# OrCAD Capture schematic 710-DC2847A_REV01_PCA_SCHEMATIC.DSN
size Custom; note: 9KHZ-7GHz SCALAR REFLECTOMETER
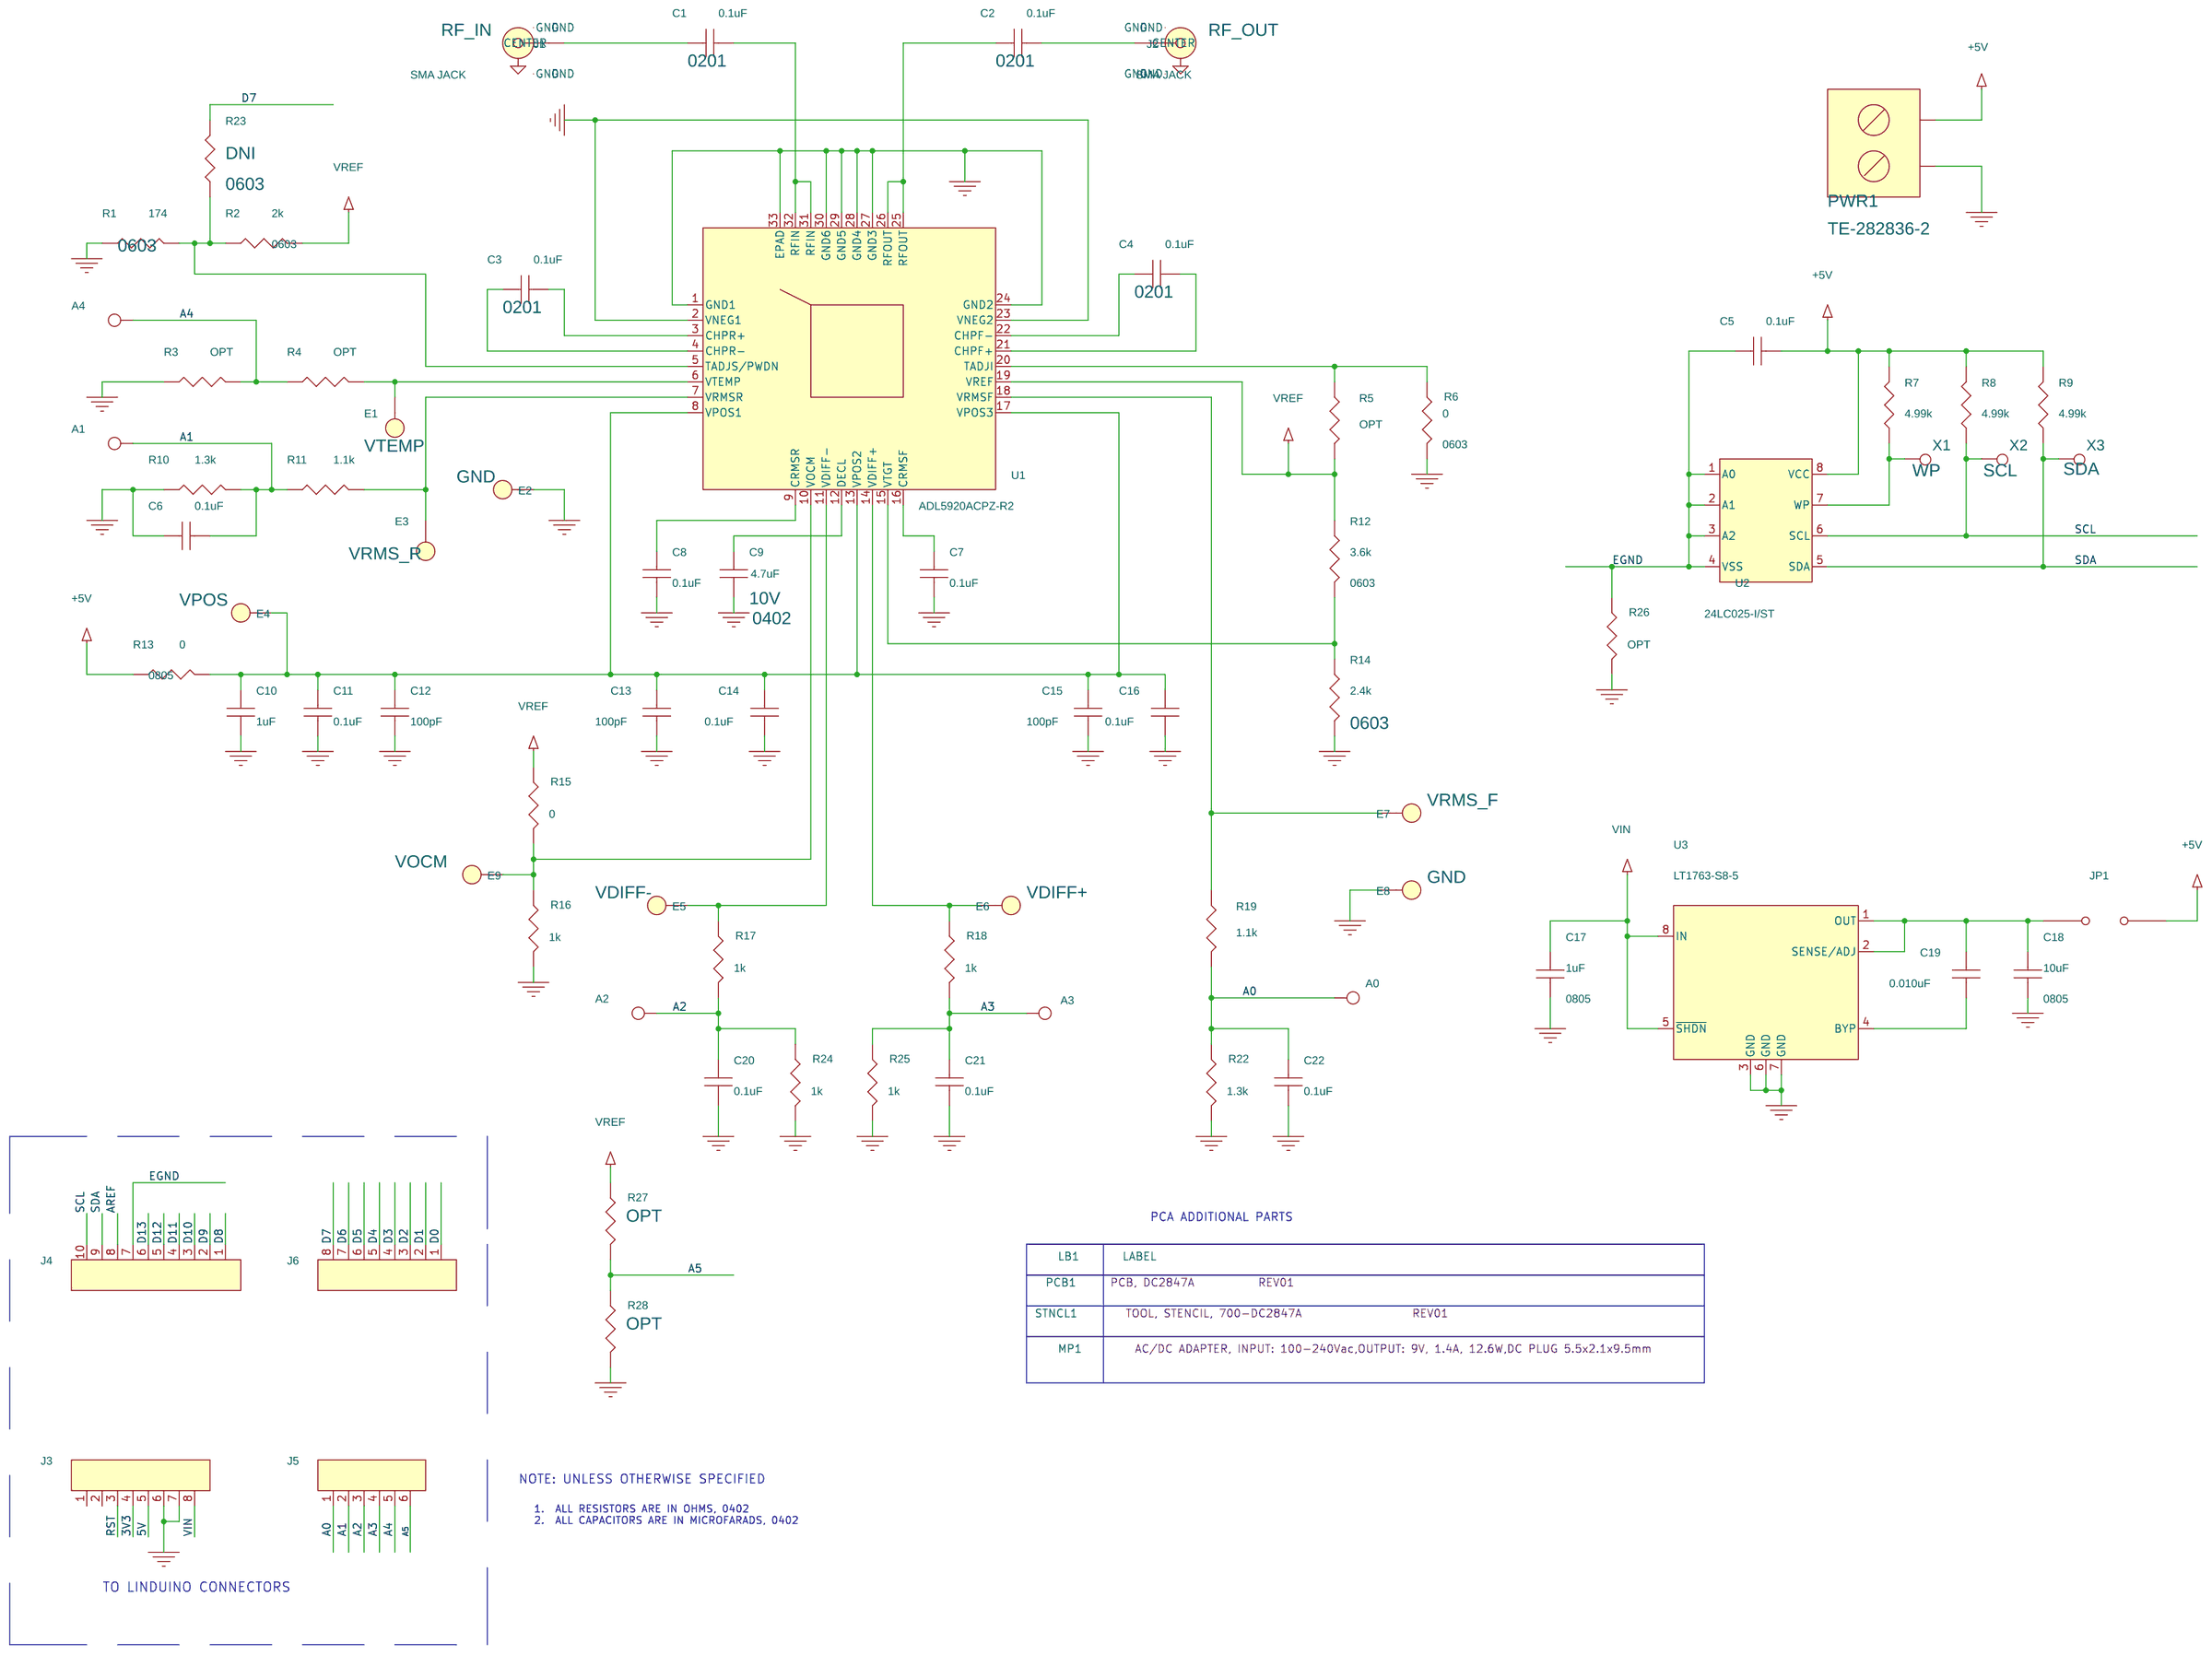
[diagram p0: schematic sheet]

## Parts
A0  PAD060-SMT-T  [PAD060-SMT-T]
A1  PAD060-SMT-T  [PAD060-SMT-T]
A2  PAD060-SMT-T  [PAD060-SMT-T]
A3  PAD060-SMT-T  [PAD060-SMT-T]
A4  PAD060-SMT-T  [PAD060-SMT-T]
C1  0.1uF  [CC0201N]
C2  0.1uF  [CC0201N]
C3  0.1uF  [CC0201N]
C4  0.1uF  [CC0201N]
C5  0.1uF  [CC0402N]
C6  0.1uF  [CC0402N]
C7  0.1uF  [CC0402N]
C8  0.1uF  [CC0402N]
C9  4.7uF  [CC0402N]
C10  1uF  [CC0402N]
C11  0.1uF  [CC0402N]
C12  100pF  [CC0402N]
C13  100pF  [CC0402N]
C14  0.1uF  [CC0402N]
C15  100pF  [CC0402N]
C16  0.1uF  [CC0402N]
C17  1uF  [CC0805N]
C18  10uF  [CC0805N]
C19  0.010uF  [CC0402N]
C20  0.1uF  [CC0402N]
C21  0.1uF  [CC0402N]
C22  0.1uF  [CC0402N]
E1  TEST POINT  [MILLMAX2308]
E2  TEST POINT  [MILLMAX2308]
E3  TEST POINT  [MILLMAX2308]
E4  TEST POINT  [MILLMAX2308]
E5  TEST POINT  [MILLMAX2308]
E6  TEST POINT  [MILLMAX2308]
E7  TEST POINT  [MILLMAX2308]
E8  TEST POINT  [MILLMAX2308]
E9  TEST POINT  [MILLMAX2308]
J1  SMA JACK  [CINCH-142-0761-871]
J2  SMA JACK  [CINCH-142-0761-871]
J3  SOCKET HDR.  [SAMTEC-SSQ-STR-1X8]
J4  SOCKET HDR.  [SAMTEC-SSQ-STR-1X10]
J5  SOCKET HDR.  [HD1X6-100]
J6  SOCKET HDR.  [SAMTEC-SSQ-STR-1X8]
JP1  HDR  [HD1X2-079]
LB1  LABEL  [895-0154_REV01]
MP1  AC/DC ADAPTER
PCB1  PCB, DC2847A
PWR1  TERM. BLOCK  [TE-282836-2]
R1  174  [CR0603N]
R2  2k  [CR0603N]
R3  OPT  [CR0402N]
R4  OPT  [CR0402N]
R5  OPT  [CR0402N]
R6  0  [CR0603N]
R7  4.99k  [CR0402N]
R8  4.99k  [CR0402N]
R9  4.99k  [CR0402N]
R10  1.3k  [CR0402N]
R11  1.1k  [CR0402N]
R12  3.6k  [CR0603N]
R13  0  [CR0805N]
R14  2.4k  [CR0603N]
R15  0  [CR0402N]
R16  1k  [CR0402N]
R17  1k  [CR0402N]
R18  1k  [CR0402N]
R19  1.1k  [CR0402N]
R22  1.3k  [CR0402N]
R23  OPT  [CR0603N]
R24  1k  [CR0402N]
R25  1k  [CR0402N]
R26  OPT  [CR0402N]
R27  OPT  [CR0402N]
R28  OPT  [CR0402N]
STNCL1  TOOL, STENCIL, 700-DC2847A
U1  ADL5920ACPZ-R2  [ADI-CP-32-7]
U2  24LC025-I/ST  [MICROCHIP-TSSOP-8]
U3  LT1763-S8-5  [LTC-S8-8-1610(S8)]
X1  E-SMT-060  [PAD060-SMT-T]
X2  E-SMT-060  [PAD060-SMT-T]
X3  E-SMT-060  [PAD060-SMT-T]

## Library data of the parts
A0-A4 = E-SMT-060_2
C1-C4 = CAP: CAP.,0.1uF,RF,16V,10%,0201; CLASS: DISCRETE; Dielectric Type: RF; Manufacturer: PASSIVE PLUS, INC.; Manufacturer PN: 0201BB104KW160; PART_NUMBER: 150-0683; Package Size: 0201; Rated Voltage: 16V; Tolerance: 10%
C5-C8 C11 C14 C16 C20-C22 = CAP: CAP.,0.1uF,X5R,50V,10%,0402; CLASS: DISCRETE; Dielectric Type: X5R; FPLIST: CC0402N,CC0402L,CC0402M; Manufacturer: AVX; Manufacturer PN: 04025D104KAT2A; PART_NUMBER: 150-3561; Package Size: 0402; Package Type: Surface Mount, MLCC; Rated Voltage: 50V; Temperature Coefficient: X5R; Tolerance: 10%
C9 = CAP: CAP.,4.7uF,X5R,10V,10%,0402; CLASS: DISCRETE; Dielectric Type: X5R; FPLIST: CC0402N,CC0402L,CC0402M; Manufacturer: TDK; Manufacturer PN: C1005X5R1A475K050BC; PART_NUMBER: 150-2275; Package Size: 0402; Rated Voltage: 10V; Tolerance: 10%
C10 = CAP: CAP.,1uF,X5R,10V,10%,0402; CLASS: DISCRETE; Dielectric Type: X5R; FPLIST: CC0402N,CC0402L,CC0402M; Manufacturer: MURATA; Manufacturer PN: GRM155R61A105KE15D; PART_NUMBER: 150-3493; Package Size: 0402; Rated Voltage: 10V; Tolerance: 10%
C12 C13 C15 = CAP: CAP.,100pF,X7R,50V,10%,0402; CLASS: DISCRETE; Dielectric Type: X7R; FPLIST: CC0402N,CC0402L,CC0402M; Manufacturer: AVX; Manufacturer PN: 04025C101KAT2A; PART_NUMBER: 150-2079; Package Size: 0402; Rated Voltage: 50V; Tolerance: 10%
C17 = CAP: CAP.,1uF,X7R,10V,10%,0805; CLASS: DISCRETE; Dielectric Type: X7R; FPLIST: CC0805N,CC0805L,CC0805M; Manufacturer: AVX; Manufacturer PN: 0805ZC105KAT2A; PART_NUMBER: 150-0141; Package Size: 0805; Rated Voltage: 10V; Tolerance: 10%
C18 = CAP: CAP.,10uF,X5R,10V,10%,0805; CLASS: DISCRETE; Dielectric Type: X5R; FPLIST: CC0805N,CC0805L,CC0805M; Manufacturer: MURATA; Manufacturer PN: GRM21BR61A106KE19L; PART_NUMBER: 150-0224; Package Size: 0805; Rated Voltage: 10V; Tolerance: 10%
C19 = CAP: CAP.,0.010uF,X7R,25V,10%,0402; CLASS: DISCRETE; Dielectric Type: X7R; FPLIST: CC0402N,CC0402L,CC0402M; Manufacturer: KEMET; Manufacturer PN: C0402C103K3RACTU; PART_NUMBER: 150-0477; Package Size: 0402; Rated Voltage: 25V; Tolerance: 10%
E1 = TEST_POINT_.156_MILL-MAX_2308: TEST POINT,TURRET,0.064",MTG. HOLE; 1: VTEMP; CLASS: IO; Manufacturer: MILL-MAX; Manufacturer PN: 2308-2-00-80-00-00-07-0; PART_NUMBER: 260-0004
E2 E8 = TEST_POINT_.156_MILL-MAX_2308: TEST POINT,TURRET,0.064",MTG. HOLE; 1: GND; CLASS: IO; Manufacturer: MILL-MAX; Manufacturer PN: 2308-2-00-80-00-00-07-0; PART_NUMBER: 260-0004
E3 = TEST_POINT_.156_MILL-MAX_2308: TEST POINT,TURRET,0.064",MTG. HOLE; 1: VRMS_R; CLASS: IO; Manufacturer: MILL-MAX; Manufacturer PN: 2308-2-00-80-00-00-07-0; PART_NUMBER: 260-0004
E4 = TEST_POINT_.156_MILL-MAX_2308: TEST POINT,TURRET,0.064",MTG. HOLE; 1: VPOS; CLASS: IO; Manufacturer: MILL-MAX; Manufacturer PN: 2308-2-00-80-00-00-07-0; PART_NUMBER: 260-0004
E5 = TEST_POINT_.156_MILL-MAX_2308: TEST POINT,TURRET,0.064",MTG. HOLE; 1: VDIFF-; CLASS: IO; Manufacturer: MILL-MAX; Manufacturer PN: 2308-2-00-80-00-00-07-0; PART_NUMBER: 260-0004
E6 = TEST_POINT_.156_MILL-MAX_2308: TEST POINT,TURRET,0.064",MTG. HOLE; 1: VDIFF+; CLASS: IO; Manufacturer: MILL-MAX; Manufacturer PN: 2308-2-00-80-00-00-07-0; PART_NUMBER: 260-0004
E7 = TEST_POINT_.156_MILL-MAX_2308: TEST POINT,TURRET,0.064",MTG. HOLE; 1: VRMS_F; CLASS: IO; Manufacturer: MILL-MAX; Manufacturer PN: 2308-2-00-80-00-00-07-0; PART_NUMBER: 260-0004
E9 = TEST_POINT_.156_MILL-MAX_2308: TEST POINT,TURRET,0.064",MTG. HOLE; 1: VOCM; CLASS: IO; Manufacturer: MILL-MAX; Manufacturer PN: 2308-2-00-80-00-00-07-0; PART_NUMBER: 260-0004
J1 = CONN_SMA_5PIN: CONN.,SMA JACK,RCPT,END LAUNCH,STR, 50 OHMS, Au; 1: RF_IN; CLASS: IO; Manufacturer: CINCH/ BEL; Manufacturer PN: 142-0761-871; PART_NUMBER: 250-0775
J2 = CONN_SMA_5PIN: CONN.,SMA JACK,RCPT,END LAUNCH,STR, 50 OHMS, Au; 1: RF_OUT; CLASS: IO; Manufacturer: CINCH/ BEL; Manufacturer PN: 142-0761-871; PART_NUMBER: 250-0775
J3 J6 = CON8: CONN.,SOCKET HDR.,RCPT,1x8,2.54mm,VERT, STR, THT,10mm CT LGTH, Au; CLASS: IO; FPLIST: SAMTEC-SSQ-STR-1X8,HD1X8-100; Manufacturer: SAMTEC; Manufacturer PN: SSQ-108-03-G-S; PART_NUMBER: 250-0895
J4 = CON-SOCKET-1X10-2.54MM: CONN.,SOCKET HDR.,RCPT.,1x10,2.54mm,VERT, STR, THT,10mm CT LGTH, Au; CLASS: IO; Manufacturer: SAMTEC; Manufacturer PN: SSQ-110-03-G-S; PART_NUMBER: 250-0894
J5 = CON6: CONN.,SOCKET HDR.,RCPT,1x6,2.54mm,VERT, STR, THT,10mm CT LGTH, Au; CLASS: IO; FPLIST: SAMTEC-SSQ-STR-1X6,HD1X6-100; Manufacturer: SAMTEC; Manufacturer PN: SSQ-106-03-G-S; PART_NUMBER: 250-0896
JP1 = JUMPER_2_PIN_.079: CONN.,HDR,MALE,1x2,2mm,VERT, STR, THT,10u" AU; CLASS: IO; Manufacturer: SAMTEC; Manufacturer PN: TMM-102-02-L-S; PART_NUMBER: 250-0420
LB1 = BLANK_LABEL: LABEL SPEC, DEMO BOARD SERIAL NUMBER; Manufacturer: BRADY; Manufacturer PN: THT-96-717-10; PART_NUMBER: 895-0154
MP1 = BLANK_PINLESS_MECHANICAL_PART: AC/DC ADAPTER, INPUT: 100-240Vac,OUTPUT: 9V, 1.4A, 12.6W,DC PLUG 5.5x2.1x9.5mm; CLASS: IO; Manufacturer: CUI INC.; Manufacturer PN: SWI15-9-N-P5; PART_NUMBER: 920-0055
PCB1 = BLANK_PCB_PART: BOM Notes: REV01; CLASS: DISCRETE; Manufacturer: GORILLA CIRCUITS; Manufacturer PN: 600-DC2847A; PART_NUMBER: 600-DC2847A
PWR1 = TERMINAL_BLOCK_WITH_SCREW: CONN.,TERM. BLOCK,RCPT,1x2,5mm,SIDE ENTRY, THT; CLASS: IO; Manufacturer: TE CONNECTIVITY; Manufacturer PN: 282836-2; PART_NUMBER: 250-0752
R1 = RES: RES.,174 OHMS,1%,1/10W,0603,AEC-Q200; CLASS: DISCRETE; Manufacturer: PANASONIC; Manufacturer PN: ERJ3EKF1740V; PART_NUMBER: 100-1100; Package Size: 0603; Rated Power: 1/10W; Temperature Coefficient: 100ppm; Tolerance: 1%
R2 = RES: RES.,2k OHMS,1%,1/10W,0603; CLASS: DISCRETE; FPLIST: CR0603N,CR0603L,CR0603M; Manufacturer: NIC; Manufacturer PN: NRC06F2001TRF; PART_NUMBER: 100-2313; Package Size: 0603; Rated Power: 1/10W; Temperature Coefficient: 100ppm/C; Tolerance: 1%
R3-R5 R26 = RES: RES., OPTION, 0402; CLASS: DISCRETE; FPLIST: CR0402N,CR0402L,CR0402M; PART_NUMBER: 100-0357; Package Size: 0402
R6 = RES: RES.,0 OHM,1/10W,0603; CLASS: DISCRETE; FPLIST: CR0603N,CR0603L,CR0603M; Manufacturer: YAGEO; Manufacturer PN: RC0603FR-070RL; PART_NUMBER: 100-2621; Package Size: 0603; Rated Power: 1/10W
R7-R9 = RES: RES.,4.99k OHMS,1%,1/16W,0402; CLASS: DISCRETE; FPLIST: CR0402N,CR0402L,CR0402M; Manufacturer: NIC; Manufacturer PN: NRC04F4991TRF; PART_NUMBER: 100-2625; Package Size: 0402; Rated Power: 1/16W; Temperature Coefficient: 100ppm/C; Tolerance: 1%
R10 R22 = RES: RES.,1.3k OHMS,1%,1/16W,0402,AEC-Q200; CLASS: DISCRETE; Manufacturer: NIC; Manufacturer PN: NRC04F1301TRF; PART_NUMBER: 100-1101; Package Size: 0402; Rated Power: 1/16W; Temperature Coefficient: +/-100PPM; Tolerance: 1%
R11 R19 = RES: RES.,1.1k OHMS,1%,1/16W,0402,AEC-Q200; CLASS: DISCRETE; FPLIST: CR0402N,CR0402L,CR0402M; Manufacturer: NIC; Manufacturer PN: NRC04F1101TRF; PART_NUMBER: 100-2638; Package Size: 0402; Rated Power: 1/16W; Temperature Coefficient: 100ppm/C; Tolerance: 1%
R12 = RES: RES.,3.6k OHMS,1%,1/10W,0603,AEC-Q200; CLASS: DISCRETE; FPLIST: CR0603N,CR0603L,CR0603M; Manufacturer: PANASONIC; Manufacturer PN: ERJ3EKF3601V; PART_NUMBER: 100-0110; Package Size: 0603; Rated Power: 1/10W; Temperature Coefficient: 100ppm/C; Tolerance: 1%
R13 = RES: RES.,0 OHM,1/8W,0805; CLASS: DISCRETE; FPLIST: CR0805N,CR0805L,CR0805M; Manufacturer: YAGEO; Manufacturer PN: RC0805JR-070RL; PART_NUMBER: 100-2291; Package Size: 0805; Rated Power: 1/8W; Temperature Coefficient: 300ppm
R14 = RES: RES.,2.4k OHMS,1%,1/10W,0603,AEC-Q200; CLASS: DISCRETE; Manufacturer: PANASONIC; Manufacturer PN: ERJ3EKF2401V; PART_NUMBER: 100-1102; Package Size: 0603; Rated Power: 1/10W; Temperature Coefficient: +/-100PPM; Tolerance: 1%
R15 = RES: RES.,0 OHM,1/16W,0402; CLASS: DISCRETE; FPLIST: CR0402N,CR0402L,CR0402M; Manufacturer: NIC; Manufacturer PN: NRC04ZOTRF; PART_NUMBER: 100-0025; Package Size: 0402; Rated Power: 1/16W
R16-R18 R24 R25 = RES: RES.,1k OHMS,1%,1/16W,0402; CLASS: DISCRETE; FPLIST: CR0402N,CR0402L,CR0402M; Manufacturer: NIC; Manufacturer PN: NRC04F1001TRF; PART_NUMBER: 100-2861; Package Size: 0402; Rated Power: 1/16W; Temperature Coefficient: +/-100ppm; Tolerance: 1%
R23 = RES: RES., OPTION, 0603; BOM Notes: DNI; CLASS: DISCRETE; FPLIST: CR0603N,CR0603L,CR0603M; PART_NUMBER: 100-2374; Package Size: 0603
R27 R28 = RES: RES., OPTION, 0402; BOM Notes: DNI; CLASS: DISCRETE; FPLIST: CR0402N,CR0402L,CR0402M; PART_NUMBER: 100-0357; Package Size: 0402
STNCL1 = BLANK_STENCIL_PART: BOM Notes: REV01; CLASS: DISCRETE; Manufacturer: ANALOG DEVICES INC.; Manufacturer PN: 830-DC2847A; PART_NUMBER: 830-DC2847A
U1 = ADL5920: IC,9KHz-7GHz Directional Bridge and Dual RMS Detector; CLASS: IC; Manufacturer: ANALOG DEVICES INC.
U2 = 24LC025-I_ST_TSSOP-8: IC, MEMORY,EEPROM,2Kb (256x8),TSSOP-8,400kHz; CLASS: IC; Manufacturer: Microchip; PART_NUMBER: 380-0087; Package Size: TSSOP-8; Package Type: TSSOP-8
U3 = LT1763-S8-X: IC,LDO uPOWER REGULATOR,SO-8; CLASS: IC; Manufacturer: LINEAR TECH.; Manufacturer PN: LT1763CS8-5#PBF; PART_NUMBER: LT1763CS8-5#PBF; Package Type: SO-8
X1 = E-SMT-060_0: 1: WP
X2 = E-SMT-060_0: 1: SCL
X3 = E-SMT-060_0: 1: SDA

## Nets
3V3: J3.4
5V: J3.5
+5V: C5.2 JP1.2 PWR1.1 R7.2 R8.2 R9.2 R13.1 U2.8(VCC)
GND: C6.1 C7.2 C8.2 C9.2 C10.2 C11.2 C12.2 C13.2 C14.2 C15.2 C16.2 C17.2 C18.2 C20.2 C21.2 C22.2 E2.1(A) E8.1(A) J1.2(GND) J1.3(GND) J1.4(GND) J1.5(GND) J2.2(GND) J2.3(GND) J2.4(GND) J2.5(GND) J3.6 J3.7 PWR1.2 R1.1 R3.1 R6.2 R10.1 R14.2 R16.2 R22.2 R24.2 R25.2 R26.2 R28.2 U1.1(GND1) U1.2(VNEG1) U1.23(VNEG2) U1.24(GND2) U1.27(GND3) U1.28(GND4) U1.29(GND5) U1.30(GND6) U1.33(EPAD) U3.3(GND) U3.6(GND) U3.7(GND)
VIN: C17.1 J3.8 U3.5(~{SHDN}) U3.8(IN)
A0: A0.1 C22.1 J5.1 R19.2 R22.1
A1: A1.1 C6.2 J5.2 R10.2 R11.1
A2: A2.1 C20.1 J5.3 R17.2 R24.1
A3: A3.1 C21.1 J5.4 R18.2 R25.1
A4: A4.1 J5.5 R3.2 R4.1
A5: J5.6 R27.2 R28.1
AREF: J4.8
D0: J6.1
D1: J6.2
D2: J6.3
D3: J6.4
D4: J6.5
D5: J6.6
D6: J6.7
D7: J6.8 R23.2
D8: J4.1
D9: J4.2
D10: J4.3
D11: J4.4
D12: J4.5
D13: J4.6
EGND: C5.1 J4.7 R26.1 U2.1(A0) U2.2(A1) U2.3(A2) U2.4(VSS)
RST: J3.3
SCL: J4.10 R8.1 U2.6(SCL) X2.1
SDA: J4.9 R9.1 U2.5(SDA) X3.1
VREF: R2.2 R5.2 R12.1 R15.1 R27.1 U1.19(VREF)
N17028426: C1.1 J1.1(CENTER)
N17028429: C1.2 U1.31(RFIN) U1.32(RFIN)
N17028487: C2.2 J2.1(CENTER)
N17028489: C2.1 U1.25(RFOUT) U1.26(RFOUT)
N17029150: C3.2 U1.3(CHPR+)
N17029157: C3.1 U1.4(CHPR-)
N17029227: C4.1 U1.22(CHPF-)
N17029236: C4.2 U1.21(CHPF+)
N17029375: R1.2 R2.1 R23.1 U1.5(TADJS/PWDN)
N17029390: E3.1(A) R11.2 U1.7(VRMSR)
N17030385: E1.1(A) R4.2 U1.6(VTEMP)
N17031177: C10.1 C11.1 C12.1 C13.1 C14.1 C15.1 C16.1 E4.1(A) R13.2 U1.8(VPOS1) U1.13(VPOS2) U1.17(VPOS3)
N17032577: C8.1 U1.9(CRMSR)
N17032671: E9.1(A) R15.2 R16.1 U1.10(VOCM)
N17033492: E5.1(A) R17.1 U1.11(VDIFF-)
N17034115: E6.1(A) R18.1 U1.14(VDIFF+)
N17035271: C9.1 U1.12(DECL)
N17036041: R12.2 R14.1 U1.15(VTGT)
N17036226: C7.1 U1.16(CRMSF)
N17036634: E7.1(A) R19.1 U1.18(VRMSF)
N17036784: R5.1 R6.1 U1.20(TADJI)
N17037196: R7.1 U2.7(WP) X1.1
N17037775: C18.1 C19.1 JP1.1 U3.1(OUT) U3.2(SENSE/ADJ)
N17037780: C19.2 U3.4(BYP)

Not connected (* = marked no-connect by the designer): J3 1 2

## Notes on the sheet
- PCA ADDITIONAL PARTS
- NOTE: UNLESS OTHERWISE SPECIFIED
- 1.  ALL RESISTORS ARE IN OHMS, 0402
  2.  ALL CAPACITORS ARE IN MICROFARADS, 0402
- TO LINDUINO CONNECTORS
